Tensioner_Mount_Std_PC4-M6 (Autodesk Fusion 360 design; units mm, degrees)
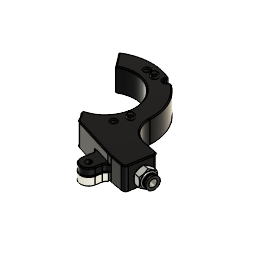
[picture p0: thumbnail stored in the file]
part number: Tensioner_Mount_Std
description: STEP AP214
part number: PC4-M6
base_feature "Base Feature1"
move "Move1"
sketch "Sketch1" plane through (46.7389, -8.3937, 0) normal (0.9843, -0.1768, 0) x axis (0.1768, 0.9843, 0)
  line L1 (-9.4532, -121) -> (-21.8532, -121)
  line L2 (-9.4532, -109) -> (-9.4532, -121)
  line L3 (-21.8532, -109) -> (-9.4532, -109)
  line L4 (-21.8532, -121) -> (-21.8532, -109)
  line L5 (-13.7064, -110.3) -> (-17.6001, -110.3)
  line L6 (-12.3298, -111.6766) -> (-13.7064, -110.3)
  line L7 (-17.6001, -110.3) -> (-18.9766, -111.6766)
  arc A1 centre (-15.6532, -115) radius 4.7 clockwise from (-12.3298, -111.6766) to (-18.9766, -111.6766)
  circle C1 centre (-15.6532, -115) radius 4.7
  circle C2 centre (-15.6532, -115) radius 5.3519
  circle C3 centre (-15.6532, -115) radius 3.0703
  concentric A1 C1
  concentric C1 C2
  concentric C1 C3
extrude "Extrude1" add sketch "Sketch1" profile of L5 L6 A1 L7 C1 C2 C3 against normal blind 8
chamfer "Chamfer1" distance 0.3
thread "Thread1" ThreadOffset 0 ThreadLength 10
move "Move2"
base_feature "Base Feature1"
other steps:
create_component "CreateComponent1"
